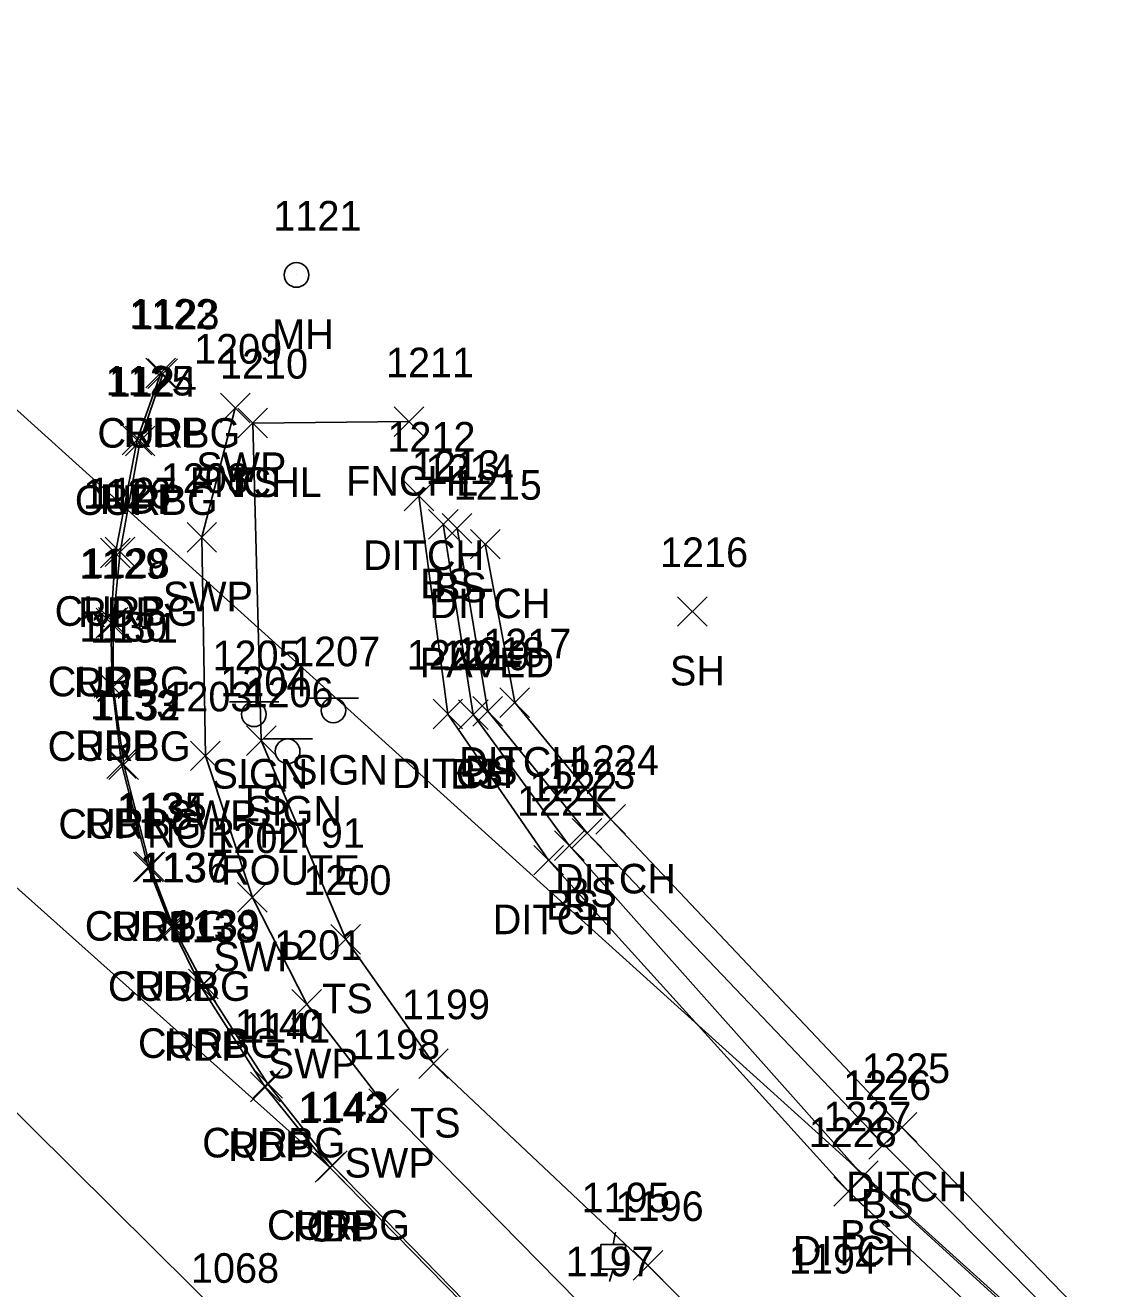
# Model space of a CAD drawing. Extents: x 1688195 to 1692013, y 424605 to 441234.
# Drawn here: x 1691818.4 to 1691891.2, y 439333.1 to 439418.5 of the extents above; entities that cross this region are included whole.
import ezdxf

# ---------------------------------------------------------------- set-up
doc = ezdxf.new("R2010")
doc.units = 0
for name, color, linetype in [('D_A', 7, 'Continuous'), ('D_C', 7, 'Continuous'), ('D_I', 7, 'Continuous'), ('D_TIC', 7, 'Continuous'), ('DCP', 7, 'Continuous'), ('DD', 7, 'Continuous'), ('L_A', 7, 'Continuous'), ('L_I', 7, 'Continuous'), ('L_TIC', 7, 'Continuous'), ('LELB', 7, 'Continuous'), ('LFNC', 7, 'Continuous'), ('P_A', 7, 'Continuous'), ('P_I', 7, 'Continuous'), ('P_TIC', 7, 'Continuous'), ('PET', 7, 'Continuous'), ('PRC', 7, 'Continuous'), ('R_A', 7, 'Continuous'), ('R_I', 7, 'Continuous'), ('R_TIC', 7, 'Continuous'), ('RC', 7, 'Continuous'), ('RSW', 7, 'Continuous'), ('S_A', 7, 'Continuous'), ('S_C', 7, 'Continuous'), ('S_I', 7, 'Continuous'), ('SSGN', 7, 'Continuous'), ('U_A', 7, 'Continuous'), ('U_I', 7, 'Continuous'), ('ULP', 7, 'Continuous'), ('UUMH', 7, 'Continuous')]:
    doc.layers.add(name, color=color, linetype=linetype)

msp = doc.modelspace()

# ---------------------------------------------------------------- linework, layer by layer
at = {"layer": 'D_TIC'}
for points in [[(1691844.001, 439385.653), (1691846.001, 439387.653)], [(1691846.001, 439385.653), (1691844.001, 439387.653)], [(1691848.482, 439382.397), (1691850.482, 439384.397)], [(1691850.482, 439382.397), (1691848.482, 439384.397)], [(1691850.476, 439371.687), (1691852.476, 439373.687)], [(1691852.476, 439371.687), (1691850.476, 439373.687)], [(1691845.957, 439370.914), (1691847.957, 439372.914)], [(1691847.957, 439370.914), (1691845.957, 439372.914)], [(1691856.963, 439363.796), (1691858.963, 439365.796)], [(1691858.963, 439363.796), (1691856.963, 439365.796)], [(1691852.76, 439361.044), (1691854.76, 439363.044)], [(1691854.76, 439361.044), (1691852.76, 439363.044)], [(1691876.631, 439342.986), (1691878.631, 439344.986)], [(1691878.631, 439342.986), (1691876.631, 439344.986)], [(1691873.032, 439338.657), (1691875.032, 439340.657)], [(1691875.032, 439338.657), (1691873.032, 439340.657)]]:
    msp.add_lwpolyline(points, dxfattribs=at)
at = {"layer": 'DCP'}
msp.add_lwpolyline([(1691949.159, 439273.864), (1691789.035, 439418.458)], dxfattribs=at)
at = {"layer": 'DD'}
for points in [[(1691845.001, 439386.653), (1691846.957, 439371.914), (1691853.76, 439362.044), (1691874.032, 439339.657), (1691896.104, 439318.91), (1691934.444, 439282.927), (1691949.727, 439270.289), (1691969.734, 439279.956), (1691978.582, 439270.803)], [(1691849.482, 439383.397), (1691851.476, 439372.687), (1691857.963, 439364.796), (1691877.631, 439343.986), (1691899.361, 439321.571), (1691937.96, 439287.208), (1691947.813, 439278.163), (1691953.235, 439277.559), (1691972.915, 439286.296), (1691980.771, 439274.159), (1691984.62, 439267.717)]]:
    msp.add_lwpolyline(points, dxfattribs=at)
at = {"layer": 'L_TIC'}
for points in [[(1691832.776, 439390.583), (1691834.776, 439392.583)], [(1691834.776, 439390.583), (1691832.776, 439392.583)], [(1691832.776, 439390.583), (1691834.776, 439392.583)], [(1691834.776, 439390.583), (1691832.776, 439392.583)], [(1691843.337, 439390.676), (1691845.337, 439392.676)], [(1691845.337, 439390.676), (1691843.337, 439392.676)], [(1691845.65, 439383.738), (1691847.65, 439385.738)], [(1691847.65, 439383.738), (1691845.65, 439385.738)], [(1691846.582, 439383.469), (1691848.582, 439385.469)], [(1691848.582, 439383.469), (1691846.582, 439385.469)], [(1691862.474, 439377.849), (1691864.474, 439379.849)], [(1691864.474, 439377.849), (1691862.474, 439379.849)], [(1691847.676, 439370.881), (1691849.676, 439372.881)], [(1691849.676, 439370.881), (1691847.676, 439372.881)], [(1691848.654, 439371.104), (1691850.654, 439373.104)], [(1691850.654, 439371.104), (1691848.654, 439373.104)], [(1691833.354, 439369.122), (1691835.354, 439371.122)], [(1691835.354, 439369.122), (1691833.354, 439371.122)], [(1691855.364, 439362.867), (1691857.364, 439364.867)], [(1691857.364, 439362.867), (1691855.364, 439364.867)], [(1691854.161, 439362.031), (1691856.161, 439364.031)], [(1691856.161, 439362.031), (1691854.161, 439364.031)], [(1691839.055, 439355.702), (1691841.055, 439357.702)], [(1691841.055, 439355.702), (1691839.055, 439357.702)], [(1691844.989, 439347.301), (1691846.989, 439349.301)], [(1691846.989, 439347.301), (1691844.989, 439349.301)], [(1691875.408, 439341.833), (1691877.408, 439343.833)], [(1691877.408, 439341.833), (1691875.408, 439343.833)], [(1691874.02, 439339.722), (1691876.02, 439341.722)], [(1691876.02, 439339.722), (1691874.02, 439341.722)], [(1691859.472, 439333.665), (1691861.472, 439335.665)], [(1691861.472, 439333.665), (1691859.472, 439335.665)]]:
    msp.add_lwpolyline(points, dxfattribs=at)
at = {"layer": 'LELB'}
for points in [[(1691975.613, 439270.604), (1691971.416, 439266.02), (1691960.529, 439259.243), (1691939.22, 439264.039), (1691915.683, 439283.723), (1691886.972, 439308.046), (1691860.472, 439334.665), (1691845.989, 439348.301), (1691840.055, 439356.702), (1691834.354, 439370.122), (1691833.776, 439391.583)], [(1691846.65, 439384.738), (1691848.676, 439371.881), (1691855.161, 439363.031), (1691875.02, 439340.722), (1691897.71, 439320.027), (1691935.729, 439284.323), (1691949.052, 439272.369), (1691970.057, 439281.458), (1691980.121, 439271.732), (1691983.031, 439266.506)], [(1691847.582, 439384.469), (1691849.654, 439372.104), (1691856.364, 439363.867), (1691876.408, 439342.833), (1691898.398, 439320.717), (1691936.438, 439285.395), (1691950.074, 439275.355), (1691972.127, 439284.543), (1691980.121, 439271.732)]]:
    msp.add_lwpolyline(points, dxfattribs=at)
at = {"layer": 'LFNC'}
msp.add_lwpolyline([(1691833.776, 439391.583), (1691844.337, 439391.676)], dxfattribs=at)
at = {"layer": 'P_TIC'}
for points in [[(1691826.559, 439393.955), (1691828.559, 439395.955)], [(1691828.559, 439393.955), (1691826.559, 439395.955)], [(1691824.961, 439389.443), (1691826.961, 439391.443)], [(1691826.961, 439389.443), (1691824.961, 439391.443)], [(1691823.493, 439381.805), (1691825.493, 439383.805)], [(1691825.493, 439381.805), (1691823.493, 439383.805)], [(1691823.197, 439377.066), (1691825.197, 439379.066)], [(1691825.197, 439377.066), (1691823.197, 439379.066)], [(1691823.28, 439372.817), (1691825.28, 439374.817)], [(1691825.28, 439372.817), (1691823.28, 439374.817)], [(1691823.909, 439367.552), (1691825.909, 439369.552)], [(1691825.909, 439367.552), (1691823.909, 439369.552)], [(1691825.714, 439360.575), (1691827.714, 439362.575)], [(1691827.714, 439360.575), (1691825.714, 439362.575)], [(1691827.277, 439356.551), (1691829.277, 439358.551)], [(1691829.277, 439356.551), (1691827.277, 439358.551)], [(1691829.285, 439352.486), (1691831.285, 439354.486)], [(1691831.285, 439352.486), (1691829.285, 439354.486)], [(1691833.62, 439345.713), (1691835.62, 439347.713)], [(1691835.62, 439345.713), (1691833.62, 439347.713)], [(1691837.982, 439340.279), (1691839.982, 439342.279)], [(1691839.982, 439340.279), (1691837.982, 439342.279)], [(1691837.982, 439340.279), (1691839.982, 439342.279)], [(1691839.982, 439340.279), (1691837.982, 439342.279)]]:
    msp.add_lwpolyline(points, dxfattribs=at)
at = {"layer": 'PET'}
msp.add_lwpolyline([(1691827.559, 439394.955), (1691825.961, 439390.443), (1691824.493, 439382.805), (1691824.197, 439378.066), (1691824.28, 439373.817), (1691824.909, 439368.552), (1691826.714, 439361.575), (1691828.277, 439357.551), (1691830.285, 439353.486), (1691834.62, 439346.713), (1691838.982, 439341.279), (1691852.353, 439327.623), (1691876.927, 439304.468), (1691895.87, 439287.457)], dxfattribs=at)
at = {"layer": 'PRC'}
for points in [[(1691787.537, 439389.792), (1691806.095, 439370.643), (1691838.982, 439341.279)], [(1691957.024, 439223.443), (1691923.547, 439249.723), (1691894.348, 439275.353), (1691862.957, 439302.592), (1691832.423, 439330.487), (1691805.17, 439357.497)]]:
    msp.add_lwpolyline(points, dxfattribs=at)
at = {"layer": 'R_TIC'}
for points in [[(1691826.698, 439393.916), (1691828.698, 439395.916)], [(1691828.698, 439393.916), (1691826.698, 439395.916)], [(1691831.593, 439391.597), (1691833.593, 439393.597)], [(1691833.593, 439391.597), (1691831.593, 439393.597)], [(1691825.17, 439389.373), (1691827.17, 439391.373)], [(1691827.17, 439389.373), (1691825.17, 439391.373)], [(1691829.336, 439382.859), (1691831.336, 439384.859)], [(1691831.336, 439382.859), (1691829.336, 439384.859)], [(1691823.809, 439381.88), (1691825.809, 439383.88)], [(1691825.809, 439381.88), (1691823.809, 439383.88)], [(1691823.344, 439377.115), (1691825.344, 439379.115)], [(1691825.344, 439377.115), (1691823.344, 439379.115)], [(1691823.336, 439372.749), (1691825.336, 439374.749)], [(1691825.336, 439372.749), (1691823.336, 439374.749)], [(1691829.576, 439368.096), (1691831.576, 439370.096)], [(1691831.576, 439368.096), (1691829.576, 439370.096)], [(1691824.062, 439367.496), (1691826.062, 439369.496)], [(1691826.062, 439367.496), (1691824.062, 439369.496)], [(1691825.846, 439360.604), (1691827.846, 439362.604)], [(1691827.846, 439360.604), (1691825.846, 439362.604)], [(1691832.754, 439358.527), (1691834.754, 439360.527)], [(1691834.754, 439358.527), (1691832.754, 439360.527)], [(1691827.402, 439356.538), (1691829.402, 439358.538)], [(1691829.402, 439356.538), (1691827.402, 439358.538)], [(1691829.439, 439352.686), (1691831.439, 439354.686)], [(1691831.439, 439352.686), (1691829.439, 439354.686)], [(1691836.427, 439351.308), (1691838.427, 439353.308)], [(1691838.427, 439351.308), (1691836.427, 439353.308)], [(1691833.776, 439345.958), (1691835.776, 439347.958)], [(1691835.776, 439345.958), (1691833.776, 439347.958)], [(1691841.614, 439344.598), (1691843.614, 439346.598)], [(1691843.614, 439344.598), (1691841.614, 439346.598)], [(1691838.157, 439340.394), (1691840.157, 439342.394)], [(1691840.157, 439340.394), (1691838.157, 439342.394)]]:
    msp.add_lwpolyline(points, dxfattribs=at)
at = {"layer": 'RC'}
msp.add_lwpolyline([(1691827.698, 439394.916), (1691826.17, 439390.373), (1691824.809, 439382.88), (1691824.344, 439378.115), (1691824.336, 439373.749), (1691825.062, 439368.496), (1691826.846, 439361.604), (1691828.402, 439357.538), (1691830.439, 439353.686), (1691834.776, 439346.958), (1691839.157, 439341.394), (1691852.504, 439327.715), (1691876.907, 439304.531), (1691896.006, 439287.533), (1691912.05, 439273.882), (1691927.887, 439261.022), (1691934.61, 439255.828), (1691939.482, 439252.554), (1691945.382, 439250.443), (1691949.024, 439249.75)], dxfattribs=at)
at = {"layer": 'RSW'}
msp.add_lwpolyline([(1691977.456, 439268.158), (1691972.672, 439263.178), (1691966.618, 439257.976), (1691961.856, 439255.834), (1691956.783, 439255.299), (1691947.569, 439255.86), (1691941.633, 439257.352), (1691936.742, 439260.655), (1691912.896, 439280.301), (1691884.494, 439305.003), (1691857.041, 439330.929), (1691842.614, 439345.598), (1691837.427, 439352.308), (1691833.754, 439359.527), (1691830.576, 439369.096), (1691830.336, 439383.859), (1691832.593, 439392.597)], dxfattribs=at)
at = {"layer": 'SSGN'}
for p, q in [((1691832.206, 439372.734), (1691835.539, 439372.734)), ((1691837.58, 439373), (1691840.913, 439373)), ((1691833.853, 439371.901), (1691833.853, 439371.901)), ((1691839.227, 439372.167), (1691839.227, 439372.167)), ((1691834.484, 439370.235), (1691837.818, 439370.235)), ((1691836.131, 439369.401), (1691836.131, 439369.401))]:
    msp.add_line(p, q, dxfattribs=at)
for centre in [(1691833.853, 439371.901), (1691839.227, 439372.167), (1691836.131, 439369.401)]:
    msp.add_circle(centre, 0.833, dxfattribs=at)
at = {"layer": 'ULP'}
for p, q in [((1691858.287, 439336.92), (1691858.121, 439336.086)), ((1691857.287, 439334.42), (1691857.287, 439336.086)), ((1691857.287, 439336.086), (1691858.954, 439336.086)), ((1691858.954, 439336.086), (1691858.954, 439334.42)), ((1691858.121, 439335.253), (1691858.121, 439335.253)), ((1691858.954, 439334.42), (1691857.287, 439334.42)), ((1691857.871, 439333.586), (1691858.121, 439334.42))]:
    msp.add_line(p, q, dxfattribs=at)
at = {"layer": 'UUMH'}
for p, q in [((1691836.73, 439401.587), (1691836.73, 439401.587)), ((1691837.563, 439401.587), (1691837.563, 439401.587))]:
    msp.add_line(p, q, dxfattribs=at)
msp.add_circle((1691836.73, 439401.587), 0.833, dxfattribs=at)

# ---------------------------------------------------------------- texts
at = {"layer": 'D_A'}
for p in [(1691841.238, 439381.653), (1691845.718, 439378.397), (1691847.712, 439367.687), (1691843.193, 439366.914), (1691854.199, 439359.796), (1691849.996, 439357.044), (1691873.867, 439338.986), (1691870.268, 439334.657)]:
    msp.add_text('DITCH', height=2, dxfattribs=at).set_placement(p)
at = {"layer": 'D_C'}
msp.add_text('PAVED', height=2, dxfattribs=at).set_placement((1691845.065, 439374.397))
at = {"layer": 'D_I'}
for s, p in [('1212', (1691842.875, 439389.653)), ('1215', (1691847.356, 439386.397)), ('1217', (1691849.35, 439375.687)), ('1220', (1691844.177, 439374.914)), ('1224', (1691855.27, 439367.796)), ('1221', (1691851.634, 439365.044)), ('1225', (1691874.938, 439346.986)), ('1228', (1691871.339, 439342.657))]:
    msp.add_text(s, height=2, dxfattribs=at).set_placement(p)
at = {"layer": 'L_A'}
for s, p in [('FNCHL', (1691829.524, 439386.583)), ('TS', (1691832.185, 439386.583)), ('FNCHL', (1691840.085, 439386.676)), ('BS', (1691845.091, 439379.738)), ('BS', (1691846.023, 439379.469)), ('SH', (1691861.962, 439373.849)), ('BS', (1691847.117, 439366.881)), ('BS', (1691848.095, 439367.104)), ('TS', (1691832.763, 439365.122)), ('BS', (1691854.805, 439358.867)), ('BS', (1691853.602, 439358.031)), ('TS', (1691838.465, 439351.702)), ('TS', (1691844.399, 439343.301)), ('BS', (1691874.849, 439337.833)), ('BS', (1691873.461, 439335.722))]:
    msp.add_text(s, height=2, dxfattribs=at).set_placement(p)
at = {"layer": 'L_I'}
for s, p in [('1210', (1691831.563, 439394.583)), ('1210', (1691831.563, 439394.583)), ('1211', (1691842.778, 439394.676)), ('1213', (1691844.524, 439387.738)), ('1214', (1691845.456, 439387.469)), ('1216', (1691861.293, 439381.849)), ('1219', (1691846.543, 439374.881)), ('1218', (1691847.528, 439375.104)), ('1204', (1691831.582, 439373.122)), ('1223', (1691853.671, 439366.867)), ('1222', (1691852.468, 439366.031)), ('1200', (1691837.197, 439359.702)), ('1199', (1691843.855, 439351.301)), ('1226', (1691873.66, 439345.833)), ('1227', (1691872.327, 439343.722)), ('1196', (1691858.291, 439337.665))]:
    msp.add_text(s, height=2, dxfattribs=at).set_placement(p)
at = {"layer": 'P_A'}
for s, p in [('RDP', (1691825.048, 439389.955)), ('RDP', (1691823.449, 439385.443)), ('RDP', (1691821.981, 439377.805)), ('RDP', (1691821.686, 439373.066)), ('RDP', (1691821.768, 439368.817)), ('RDP', (1691822.398, 439363.552)), ('RDP', (1691824.202, 439356.575)), ('RDP', (1691825.765, 439352.551)), ('RDP', (1691827.773, 439348.486)), ('RDP', (1691832.108, 439341.713)), ('RDP', (1691836.47, 439336.279)), ('CR', (1691837.415, 439336.279))]:
    msp.add_text(s, height=2, dxfattribs=at).set_placement(p)
at = {"layer": 'P_I'}
for s, p in [('1122', (1691825.433, 439397.955)), ('1125', (1691823.835, 439393.443)), ('1126', (1691822.312, 439385.805)), ('1129', (1691822.064, 439381.066)), ('1130', (1691822.068, 439376.817)), ('1133', (1691822.783, 439371.552)), ('1134', (1691824.588, 439364.575)), ('1137', (1691826.151, 439360.551)), ('1138', (1691828.159, 439356.486)), ('1141', (1691833.061, 439349.713)), ('1142', (1691836.856, 439344.279)), ('1142', (1691836.856, 439344.279)), ('1068', (1691829.604, 439333.487))]:
    msp.add_text(s, height=2, dxfattribs=at).set_placement(p)
at = {"layer": 'R_A'}
for s, p in [('CURBG', (1691823.28, 439389.916)), ('SWP', (1691829.955, 439387.597)), ('CURBG', (1691821.753, 439385.373)), ('SWP', (1691827.699, 439378.859)), ('CURBG', (1691820.391, 439377.88)), ('CURBG', (1691819.927, 439373.115)), ('CURBG', (1691819.918, 439368.749)), ('CURBG', (1691820.645, 439363.496)), ('SWP', (1691827.938, 439364.096)), ('CURBG', (1691822.428, 439356.604)), ('SWP', (1691831.116, 439354.527)), ('CURBG', (1691823.985, 439352.538)), ('CURBG', (1691826.022, 439348.686)), ('SWP', (1691834.79, 439347.308)), ('CURBG', (1691830.359, 439341.958)), ('SWP', (1691839.976, 439340.598)), ('CURBG', (1691834.74, 439336.394))]:
    msp.add_text(s, height=2, dxfattribs=at).set_placement(p)
at = {"layer": 'R_I'}
for s, p in [('1123', (1691825.572, 439397.916)), ('1209', (1691829.813, 439395.597)), ('1124', (1691824.044, 439393.373)), ('1208', (1691827.565, 439386.859)), ('1127', (1691822.683, 439385.88)), ('1128', (1691822.219, 439381.115)), ('1131', (1691822.777, 439376.749)), ('1203', (1691827.804, 439372.096)), ('1132', (1691822.936, 439371.496)), ('1135', (1691824.72, 439364.604)), ('1202', (1691830.982, 439362.527)), ('1136', (1691826.221, 439360.538)), ('1139', (1691828.305, 439356.686)), ('1201', (1691835.223, 439355.308)), ('1140', (1691832.563, 439349.958)), ('1198', (1691840.488, 439348.598)), ('1143', (1691837.031, 439344.394)), ('1197', (1691854.915, 439333.929))]:
    msp.add_text(s, height=2, dxfattribs=at).set_placement(p)
at = {"layer": 'S_A'}
for p in [(1691830.991, 439366.881), (1691836.364, 439367.146), (1691833.269, 439364.381)]:
    msp.add_text('SIGN', height=2, dxfattribs=at).set_placement(p)
at = {"layer": 'S_C'}
for s, p in [('NORTH I 91', (1691826.636, 439362.881)), ('ROUTE', (1691831.639, 439360.381))]:
    msp.add_text(s, height=2, dxfattribs=at).set_placement(p)
at = {"layer": 'S_I'}
for s, p in [('1205', (1691831.062, 439374.881)), ('1207', (1691836.435, 439375.146)), ('1206', (1691833.285, 439372.381)), ('1194', (1691870.005, 439334.116))]:
    msp.add_text(s, height=2, dxfattribs=at).set_placement(p)
at = {"layer": 'U_A'}
msp.add_text('MH', height=2, dxfattribs=at).set_placement((1691835.092, 439396.587))
at = {"layer": 'U_I'}
for s, p in [('1121', (1691835.171, 439404.587)), ('1195', (1691855.995, 439338.253))]:
    msp.add_text(s, height=2, dxfattribs=at).set_placement(p)

doc.saveas('drawing.dxf')
